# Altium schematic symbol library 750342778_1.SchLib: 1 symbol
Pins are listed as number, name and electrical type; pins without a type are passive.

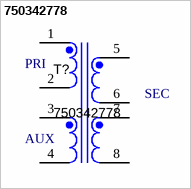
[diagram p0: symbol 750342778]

## 750342778
designator T?
TRANSFORMER, 3.5mH, 10%, THRU; Manufacturer: Wurth Elektronics; SymbolCreator: x0199378
pins: 1, 2, 3, 4, 5, 6, 7, 8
